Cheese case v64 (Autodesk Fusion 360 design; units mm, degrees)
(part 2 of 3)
sketch "Left outside" plane through (108.8712, 0, 0) normal (1, 0, 0) x axis (0, 0, -1)
  line L1 (127.4117, -56.3921) -> (0, -56.3921)
  line L2 (127.4117, 6.234) -> (127.4117, -56.3921)
  line L3 (0, 6.234) -> (127.4117, 6.234)
  line L4 (0, -56.3921) -> (0, 6.234)
  line L5 (50, 0.8053) -> (0, 0.7957)
  line L6 (4.3132, -90.1692) -> (4.3201, 6.234)
  line L7 (20.5169, -10.8331) -> (9.7193, -10.8352)
  line L8 (9.7193, -10.8352) -> (9.7181, -4.6012)
  line L9 (9.7191, -10) -> (9.7181, -4.6012)
  line L10 (9.7171, 0.7976) -> (9.7181, -4.6012)
  line L11 (20.5159, -5.4343) -> (20.5169, -10.8331)
  line L12 (20.5179, -16.2319) -> (20.5169, -10.8331)
  line L13 (31.3145, -10.8352) -> (31.3133, -4.6012)
  line L14 (31.3123, 0.7976) -> (31.3133, -4.6012)
  line L15 (52.9097, -10.8352) -> (52.9085, -4.6012)
  line L16 (52.9075, 0.7976) -> (52.9085, -4.6012)
  line L17 (74.5049, -10.8352) -> (74.5037, -4.6012)
  line L18 (74.5027, 0.7976) -> (74.5037, -4.6012)
  line L19 (96.1001, -10.8352) -> (96.0989, -4.6012)
  line L20 (96.0979, 0.7976) -> (96.0989, -4.6012)
  line L21 (117.6953, -10.8352) -> (117.6941, -4.6012)
  line L22 (117.6931, 0.7976) -> (117.6941, -4.6012)
  line L23 (9.7193, -23.3032) -> (9.7181, -17.0692)
  line L24 (9.7171, -11.6704) -> (9.7181, -17.0692)
  line L25 (31.3145, -23.3032) -> (31.3133, -17.0692)
  line L26 (31.3123, -11.6704) -> (31.3133, -17.0692)
  line L27 (52.9097, -23.3032) -> (52.9085, -17.0692)
  line L28 (52.9075, -11.6704) -> (52.9085, -17.0692)
  line L29 (74.5049, -23.3032) -> (74.5037, -17.0692)
  line L30 (74.5027, -11.6704) -> (74.5037, -17.0692)
  line L31 (96.1001, -23.3032) -> (96.0989, -17.0692)
  line L32 (96.0979, -11.6704) -> (96.0989, -17.0692)
  line L33 (117.6953, -23.3032) -> (117.6941, -17.0692)
  line L34 (117.6931, -11.6704) -> (117.6941, -17.0692)
  line L35 (9.7193, -35.7712) -> (9.7181, -29.5372)
  line L36 (9.7171, -24.1384) -> (9.7181, -29.5372)
  line L37 (31.3145, -35.7712) -> (31.3133, -29.5372)
  line L38 (31.3123, -24.1384) -> (31.3133, -29.5372)
  line L39 (52.9097, -35.7712) -> (52.9085, -29.5372)
  line L40 (52.9075, -24.1384) -> (52.9085, -29.5372)
  line L41 (74.5049, -35.7712) -> (74.5037, -29.5372)
  line L42 (74.5027, -24.1384) -> (74.5037, -29.5372)
  line L43 (96.1001, -35.7712) -> (96.0989, -29.5372)
  line L44 (96.0979, -24.1384) -> (96.0989, -29.5372)
  line L45 (117.6953, -35.7712) -> (117.6941, -29.5372)
  line L46 (117.6931, -24.1384) -> (117.6941, -29.5372)
  line L47 (9.7193, -48.2392) -> (9.7181, -42.0052)
  line L48 (9.7171, -36.6064) -> (9.7181, -42.0052)
  line L49 (31.3145, -48.2392) -> (31.3133, -42.0052)
  line L50 (31.3123, -36.6064) -> (31.3133, -42.0052)
  line L51 (52.9097, -48.2392) -> (52.9085, -42.0052)
  line L52 (52.9075, -36.6064) -> (52.9085, -42.0052)
  line L53 (74.5049, -48.2392) -> (74.5037, -42.0052)
  line L54 (74.5027, -36.6064) -> (74.5037, -42.0052)
  line L55 (96.1001, -48.2392) -> (96.0989, -42.0052)
  line L56 (96.0979, -36.6064) -> (96.0989, -42.0052)
  line L57 (117.6953, -48.2392) -> (117.6941, -42.0052)
  line L58 (117.6931, -36.6064) -> (117.6941, -42.0052)
  line L59 (42.1131, -16.2319) -> (42.1121, -10.8331)
  line L60 (42.1111, -5.4343) -> (42.1121, -10.8331)
  line L61 (63.7084, -16.2319) -> (63.7073, -10.8331)
  line L62 (63.7063, -5.4343) -> (63.7073, -10.8331)
  line L63 (85.3036, -16.2319) -> (85.3025, -10.8331)
  line L64 (85.3015, -5.4343) -> (85.3025, -10.8331)
  line L65 (106.8988, -16.2319) -> (106.8977, -10.8331)
  line L66 (106.8967, -5.4343) -> (106.8977, -10.8331)
  line L67 (20.5179, -28.6999) -> (20.5169, -23.3011)
  line L68 (20.5159, -17.9023) -> (20.5169, -23.3011)
  line L69 (42.1131, -28.6999) -> (42.1121, -23.3011)
  line L70 (42.1111, -17.9023) -> (42.1121, -23.3011)
  line L71 (63.7084, -28.6999) -> (63.7073, -23.3011)
  line L72 (63.7063, -17.9023) -> (63.7073, -23.3011)
  line L73 (85.3036, -28.6999) -> (85.3025, -23.3011)
  line L74 (85.3015, -17.9023) -> (85.3025, -23.3011)
  line L75 (106.8988, -28.6999) -> (106.8977, -23.3011)
  line L76 (106.8967, -17.9023) -> (106.8977, -23.3011)
  line L77 (20.5179, -41.1679) -> (20.5169, -35.7691)
  line L78 (20.5159, -30.3703) -> (20.5169, -35.7691)
  line L79 (42.1131, -41.1679) -> (42.1121, -35.7691)
  line L80 (42.1111, -30.3703) -> (42.1121, -35.7691)
  line L81 (63.7084, -41.1679) -> (63.7073, -35.7691)
  line L82 (63.7063, -30.3703) -> (63.7073, -35.7691)
  line L83 (85.3036, -41.1679) -> (85.3025, -35.7691)
  line L84 (85.3015, -30.3703) -> (85.3025, -35.7691)
  line L85 (106.8988, -41.1679) -> (106.8977, -35.7691)
  line L86 (106.8967, -30.3703) -> (106.8977, -35.7691)
  line L87 (20.5179, -53.6359) -> (20.5169, -48.2371)
  line L88 (20.5159, -42.8383) -> (20.5169, -48.2371)
  line L89 (42.1131, -53.6359) -> (42.1121, -48.2371)
  line L90 (42.1111, -42.8383) -> (42.1121, -48.2371)
  line L91 (63.7084, -53.6359) -> (63.7073, -48.2371)
  line L92 (63.7063, -42.8383) -> (63.7073, -48.2371)
  line L93 (85.3036, -53.6359) -> (85.3025, -48.2371)
  line L94 (85.3015, -42.8383) -> (85.3025, -48.2371)
  line L95 (106.8988, -53.6359) -> (106.8977, -48.2371)
  line L96 (106.8967, -42.8383) -> (106.8977, -48.2371)
  line L97 (31.3143, -10) -> (31.3133, -4.6012)
  line L98 (52.9095, -10) -> (52.9085, -4.6012)
  line L99 (74.5048, -10) -> (74.5037, -4.6012)
  line L100 (96.1, -10) -> (96.0989, -4.6012)
  line L101 (117.6952, -10) -> (117.6941, -4.6012)
  line L102 (9.7191, -22.468) -> (9.7181, -17.0692)
  line L103 (31.3143, -22.468) -> (31.3133, -17.0692)
  line L104 (52.9095, -22.468) -> (52.9085, -17.0692)
  line L105 (74.5048, -22.468) -> (74.5037, -17.0692)
  line L106 (96.1, -22.468) -> (96.0989, -17.0692)
  line L107 (117.6952, -22.468) -> (117.6941, -17.0692)
  line L108 (9.7191, -34.936) -> (9.7181, -29.5372)
  line L109 (31.3143, -34.936) -> (31.3133, -29.5372)
  line L110 (52.9095, -34.936) -> (52.9085, -29.5372)
  line L111 (74.5048, -34.936) -> (74.5037, -29.5372)
  line L112 (96.1, -34.936) -> (96.0989, -29.5372)
  line L113 (117.6952, -34.936) -> (117.6941, -29.5372)
  line L114 (9.7191, -47.404) -> (9.7181, -42.0052)
  line L115 (31.3143, -47.404) -> (31.3133, -42.0052)
  line L116 (52.9095, -47.404) -> (52.9085, -42.0052)
  line L117 (74.5048, -47.404) -> (74.5037, -42.0052)
  line L118 (96.1, -47.404) -> (96.0989, -42.0052)
  line L119 (117.6952, -47.404) -> (117.6941, -42.0052)
  circle C1 centre (9.7181, -4.6012) radius 5.3988
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  point P11 (9.7181, -4.6012)
  point P12 (9.7181, -4.6012)
  point P14 (20.5169, -10.8331)
  point P15 (20.5169, -10.8331)
  point P16 (9.7191, -10)
  point P17 (9.7171, 0.7976)
  point P18 (20.5169, -10.8331)
  point P20 (20.5169, -10.8331)
  point P13 (9.7193, -10.8352)
  tangent L5 C1
  tangent L6 C1
  coincident P11 P12
  perpendicular L7 L8
  coincident P14 P15
  coincident L8 P16
  coincident C1 P16
  perpendicular L5 L9
  coincident L5 P17
  coincident C1 P17
  perpendicular L5 L10
  coincident P15 P18
  perpendicular L7 L11
  coincident P15 P20
  perpendicular L7 L12
  dimension "d404" radius C1 = 5.3988 (= "radius")
  dimension "d405" distance P12 P13 = 6.234 (= "Linear Dimension-2")
  dimension "d406" distance P13 P14 = 10.7976 (= "2 * radius")
  dimension "d407" diameter = 10.7976 (= "2 * radius")
  dimension "d410" R-Pattern1-uDistance = 21.5952 (= "4 * radius")
  dimension "d414" R-Pattern2-uDistance = 21.5952 (= "4 * radius")
sketch "Left inside" plane through (102.6372, 0, 0) normal (-1, 0, 0) x axis (0, 0, 1)
  line L1 (-127.4117, 6.234) -> (0, 6.234)
  line L2 (-127.4117, -56.3921) -> (-127.4117, 6.234)
  line L3 (0, -56.3921) -> (-127.4117, -56.3921)
  line L4 (0, 6.234) -> (0, -56.3921)
  line L5 (-7.9182, -10.7976) -> (-13.317, -10.7976)
  line L6 (-18.7158, -10.7976) -> (-13.317, -10.7976)
  line L7 (-29.5135, -17.0316) -> (-24.1147, -17.0316)
  line L8 (-18.7158, -17.0316) -> (-24.1147, -17.0316)
  line L9 (-18.7158, -23.2656) -> (-13.317, -23.2656)
  line L10 (-7.9182, -23.2656) -> (-13.317, -23.2656)
  line L11 (-18.7158, -35.7336) -> (-13.317, -35.7336)
  line L12 (-7.9182, -35.7336) -> (-13.317, -35.7336)
  line L13 (-18.7158, -48.2016) -> (-13.317, -48.2016)
  line L14 (-7.9182, -48.2016) -> (-13.317, -48.2016)
  line L15 (-40.3111, -10.7976) -> (-34.9123, -10.7976)
  line L16 (-29.5135, -10.7976) -> (-34.9123, -10.7976)
  line L17 (-40.3111, -23.2656) -> (-34.9123, -23.2656)
  line L18 (-29.5135, -23.2656) -> (-34.9123, -23.2656)
  line L19 (-40.3111, -35.7336) -> (-34.9123, -35.7336)
  line L20 (-29.5135, -35.7336) -> (-34.9123, -35.7336)
  line L21 (-40.3111, -48.2016) -> (-34.9123, -48.2016)
  line L22 (-29.5135, -48.2016) -> (-34.9123, -48.2016)
  line L23 (-61.9063, -10.7976) -> (-56.5075, -10.7976)
  line L24 (-51.1087, -10.7976) -> (-56.5075, -10.7976)
  line L25 (-61.9063, -23.2656) -> (-56.5075, -23.2656)
  line L26 (-51.1087, -23.2656) -> (-56.5075, -23.2656)
  line L27 (-61.9063, -35.7336) -> (-56.5075, -35.7336)
  line L28 (-51.1087, -35.7336) -> (-56.5075, -35.7336)
  line L29 (-61.9063, -48.2016) -> (-56.5075, -48.2016)
  line L30 (-51.1087, -48.2016) -> (-56.5075, -48.2016)
  line L31 (-83.5015, -10.7976) -> (-78.1027, -10.7976)
  line L32 (-72.7039, -10.7976) -> (-78.1027, -10.7976)
  line L33 (-83.5015, -23.2656) -> (-78.1027, -23.2656)
  line L34 (-72.7039, -23.2656) -> (-78.1027, -23.2656)
  line L35 (-83.5015, -35.7336) -> (-78.1027, -35.7336)
  line L36 (-72.7039, -35.7336) -> (-78.1027, -35.7336)
  line L37 (-83.5015, -48.2016) -> (-78.1027, -48.2016)
  line L38 (-72.7039, -48.2016) -> (-78.1027, -48.2016)
  line L39 (-105.0967, -10.7976) -> (-99.6979, -10.7976)
  line L40 (-94.2991, -10.7976) -> (-99.6979, -10.7976)
  line L41 (-105.0967, -23.2656) -> (-99.6979, -23.2656)
  line L42 (-94.2991, -23.2656) -> (-99.6979, -23.2656)
  line L43 (-105.0967, -35.7336) -> (-99.6979, -35.7336)
  line L44 (-94.2991, -35.7336) -> (-99.6979, -35.7336)
  line L45 (-105.0967, -48.2016) -> (-99.6979, -48.2016)
  line L46 (-94.2991, -48.2016) -> (-99.6979, -48.2016)
  line L47 (-126.6919, -10.7976) -> (-121.2931, -10.7976)
  line L48 (-115.8943, -10.7976) -> (-121.2931, -10.7976)
  line L49 (-126.6919, -23.2656) -> (-121.2931, -23.2656)
  line L50 (-115.8943, -23.2656) -> (-121.2931, -23.2656)
  line L51 (-126.6919, -35.7336) -> (-121.2931, -35.7336)
  line L52 (-115.8943, -35.7336) -> (-121.2931, -35.7336)
  line L53 (-126.6919, -48.2016) -> (-121.2931, -48.2016)
  line L54 (-115.8943, -48.2016) -> (-121.2931, -48.2016)
  line L55 (-29.5135, -29.4996) -> (-24.1147, -29.4996)
  line L56 (-18.7158, -29.4996) -> (-24.1147, -29.4996)
  line L57 (-29.5135, -41.9676) -> (-24.1147, -41.9676)
  line L58 (-18.7158, -41.9676) -> (-24.1147, -41.9676)
  line L59 (-51.1087, -17.0316) -> (-45.7099, -17.0316)
  line L60 (-40.3111, -17.0316) -> (-45.7099, -17.0316)
  line L61 (-51.1087, -29.4996) -> (-45.7099, -29.4996)
  line L62 (-40.3111, -29.4996) -> (-45.7099, -29.4996)
  line L63 (-51.1087, -41.9676) -> (-45.7099, -41.9676)
  line L64 (-40.3111, -41.9676) -> (-45.7099, -41.9676)
  line L65 (-72.7039, -17.0316) -> (-67.3051, -17.0316)
  line L66 (-61.9063, -17.0316) -> (-67.3051, -17.0316)
  line L67 (-72.7039, -29.4996) -> (-67.3051, -29.4996)
  line L68 (-61.9063, -29.4996) -> (-67.3051, -29.4996)
  line L69 (-72.7039, -41.9676) -> (-67.3051, -41.9676)
  line L70 (-61.9063, -41.9676) -> (-67.3051, -41.9676)
  line L71 (-94.2991, -17.0316) -> (-88.9003, -17.0316)
  line L72 (-83.5015, -17.0316) -> (-88.9003, -17.0316)
  line L73 (-94.2991, -29.4996) -> (-88.9003, -29.4996)
  line L74 (-83.5015, -29.4996) -> (-88.9003, -29.4996)
  line L75 (-94.2991, -41.9676) -> (-88.9003, -41.9676)
  line L76 (-83.5015, -41.9676) -> (-88.9003, -41.9676)
  line L77 (-115.8943, -17.0316) -> (-110.4955, -17.0316)
  line L78 (-105.0967, -17.0316) -> (-110.4955, -17.0316)
  line L79 (-115.8943, -29.4996) -> (-110.4955, -29.4996)
  line L80 (-105.0967, -29.4996) -> (-110.4955, -29.4996)
  line L81 (-115.8943, -41.9676) -> (-110.4955, -41.9676)
  line L82 (-105.0967, -41.9676) -> (-110.4955, -41.9676)
  line L83 (-51.1087, -17.0316) -> (-45.7099, -17.0316)
  line L84 (-40.3111, -17.0316) -> (-45.7099, -17.0316)
  line L85 (-72.7039, -17.0316) -> (-67.3051, -17.0316)
  line L86 (-61.9063, -17.0316) -> (-67.3051, -17.0316)
  line L87 (-94.2991, -17.0316) -> (-88.9003, -17.0316)
  line L88 (-83.5015, -17.0316) -> (-88.9003, -17.0316)
  line L89 (-115.8943, -17.0316) -> (-110.4955, -17.0316)
  line L90 (-105.0967, -17.0316) -> (-110.4955, -17.0316)
  line L91 (-29.5135, -4.5636) -> (-24.1147, -4.5636)
  line L92 (-18.7158, -4.5636) -> (-24.1147, -4.5636)
  line L93 (-51.1087, -4.5636) -> (-45.7099, -4.5636)
  line L94 (-40.3111, -4.5636) -> (-45.7099, -4.5636)
  line L95 (-72.7039, -4.5636) -> (-67.3051, -4.5636)
  line L96 (-61.9063, -4.5636) -> (-67.3051, -4.5636)
  line L97 (-94.2991, -4.5636) -> (-88.9003, -4.5636)
  line L98 (-83.5015, -4.5636) -> (-88.9003, -4.5636)
  line L99 (-115.8943, -4.5636) -> (-110.4955, -4.5636)
  line L100 (-105.0967, -4.5636) -> (-110.4955, -4.5636)
  circle C1 centre (-13.317, -10.7976) radius 5.3988
  circle C2 centre (-24.1147, -17.0316) radius 5.3988
  circle C3 centre (-13.317, -23.2656) radius 5.3988
  circle C4 centre (-13.317, -35.7336) radius 5.3988
  circle C5 centre (-13.317, -48.2016) radius 5.3988
  circle C6 centre (-34.9123, -10.7976) radius 5.3988
  circle C7 centre (-34.9123, -23.2656) radius 5.3988
  circle C8 centre (-34.9123, -35.7336) radius 5.3988
  circle C9 centre (-34.9123, -48.2016) radius 5.3988
  circle C10 centre (-56.5075, -10.7976) radius 5.3988
  circle C11 centre (-56.5075, -23.2656) radius 5.3988
  circle C12 centre (-56.5075, -35.7336) radius 5.3988
  circle C13 centre (-56.5075, -48.2016) radius 5.3988
  circle C14 centre (-78.1027, -10.7976) radius 5.3988
  circle C15 centre (-78.1027, -23.2656) radius 5.3988
  circle C16 centre (-78.1027, -35.7336) radius 5.3988
  circle C17 centre (-78.1027, -48.2016) radius 5.3988
  circle C18 centre (-99.6979, -10.7976) radius 5.3988
  circle C19 centre (-99.6979, -23.2656) radius 5.3988
  circle C20 centre (-99.6979, -35.7336) radius 5.3988
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  point P9 (-13.317, -10.7976)
  point P13 (-13.317, -10.7976)
  point P11 (-24.1147, -17.0316)
  point P15 (-24.1147, -17.0316)
  point P17 (-24.1147, -17.0316)
  point P14 (-18.7158, -10.7976)
  point P10 (-7.9182, -10.7976)
  point P16 (-18.7158, -17.0316)
  point P18 (-29.5135, -17.0316)
  coincident P9 P13
  coincident P11 P15
  coincident P15 P17
  dimension "d439" diameter C1 = 10.7976 (= "2 * radius")
  dimension "d440" distance P13 P14 = 5.3988 (= "radius")
  dimension "d441" distance P10 P13 = 5.3988 (= "radius")
  dimension "d442" diameter C2 = 10.7976 (= "2 * radius")
  dimension "d443" distance P11 P16 = 5.3988 (= "radius")
  dimension "d444" distance P17 P18 = 5.3988 (= "radius")
  dimension "d448" R-Pattern1-vDistance = 21.5952 (= "4 * radius")
  dimension "d452" R-Pattern2-vDistance = 21.5952 (= "4 * radius")
  dimension "d455" R-Pattern3-uDistance = -21.5952 (= "-4 * radius")
revolve "Revolve61" sketch "Left outside" AlongAngle 360
revolve "Revolve62" sketch "Left outside" AlongAngle 360
revolve "Revolve63" sketch "Left outside" AlongAngle 360
revolve "Revolve64" sketch "Left outside" AlongAngle 360
revolve "Revolve65" sketch "Left outside" AlongAngle 360
revolve "Revolve66" sketch "Left outside" AlongAngle 360
revolve "Revolve67" sketch "Left outside" AlongAngle 360
revolve "Revolve68" sketch "Left outside" AlongAngle 360
revolve "Revolve69" sketch "Left outside" AlongAngle 360
revolve "Revolve70" sketch "Left outside" AlongAngle 360
revolve "Revolve71" sketch "Left outside" AlongAngle 360
revolve "Revolve72" sketch "Left inside" AlongAngle 360
revolve "Revolve73" sketch "Left inside" AlongAngle 360
revolve "Revolve74" sketch "Left inside" AlongAngle 360
revolve "Revolve75" sketch "Left inside" AlongAngle 360
revolve "Revolve76" sketch "Left inside" AlongAngle 360
revolve "Revolve77" sketch "Left inside" AlongAngle 360
revolve "Revolve78" sketch "Left inside" AlongAngle 360
work_plane "WorkPlane2"
mirror "Mirror5" bodies "Rechts"
combine "Combine3" bodies "Links", "Deckel", "Rechts", "Vorne"
fillet "Fillet4" radius 5.3988 (= "radius")
combine "Combine4"
combine "Combine5"
combine "Combine6"
combine "Combine7"
combine "Combine8"
extrude "Extrude16" add sketch "Feet" profile of C1 C2 C3 C4 C5 C6 C7 C8 along normal blind 2.5
extrude "Extrude17" add of existing geometry to an object
extrude "Extrude18" cut sketch "Feet" profile of C1 C2 C3 C4 C5 C6 C7 C8 along normal blind 2.5
chamfer "Chamfer5" distance 2.5
extrude "Extrude10" add sketch "Switch" profile of C1 C2 no distance stored
extrude "Extrude11" cut sketch "Switch" profile of C1 L6 L7 L8 L9 L11 L12 L13 L15 no distance stored
extrude "Extrude12" cut sketch "Switch" profile of C1 C3 L6 L7 L8 L9 L11 L12 L13 L15 no distance stored
extrude "Extrude13" add sketch "Switch" profile of C1 C2 C3 L6 L7 L8 L9 L11 L12 L13 L15 blind -2.5 from offset -2
extrude "Extrude15" add sketch "Switch" profile of C1 C3 L6 L7 L8 L9 L11 L12 L13 L15 blind 0.2 from offset -2
chamfer "Chamfer6" distance 0.4
sketch "Back" plane through (0, 0, -127.4117) normal (0, 0, -1) x axis (-1, 0, 0)
  line L1 (-108.8712, -50.1581) -> (0, -50.1581)
  line L2 (-108.8712, -56.3921) -> (-108.8712, -50.1581)
  line L3 (0, -56.3921) -> (-108.8712, -56.3921)
  line L4 (0, -50.1581) -> (0, -56.3921)
  line L5 (-6.234, 0) -> (-102.6372, 0)
  line L6 (-102.6372, -56.3921) -> (-102.6372, 6.234)
  line L7 (0, -50.1581) -> (-108.8712, -50.1581)
  line L8 (-54.4356, 0) -> (-54.4356, -50.1581)
  line L9 (-44.9562, 0) -> (-6.234, 0)
  line L10 (-6.234, -50.1581) -> (-44.9562, -50.1581)
  line L11 (-6.234, 0) -> (-6.234, -50.1581)
  line L12 (-6.5586, -3.5) -> (-8.1463, -6.25)
  line L13 (-8.1463, -0.75) -> (-6.5586, -3.5)
  line L14 (-11.3217, -0.75) -> (-8.1463, -0.75)
  line L15 (-12.9094, -3.5) -> (-11.3217, -0.75)
  line L16 (-11.3217, -6.25) -> (-12.9094, -3.5)
  line L17 (-8.1463, -6.25) -> (-11.3217, -6.25)
  line L18 (-6.234, -56.3921) -> (-6.234, 6.234)
  line L19 (-103.4724, 6.234) -> (-5.3988, 6.234)
  line L20 (-108.8712, -50.9933) -> (-108.8712, 0.8352)
  line L21 (-5.3988, -56.3921) -> (-103.4724, -56.3921)
  line L22 (0, 0.8352) -> (0, -50.9933)
  line L23 (-6.234, -50.1581) -> (-6.234, 0)
  line L24 (-102.6372, -50.1581) -> (-6.234, -50.1581)
  line L25 (-102.6372, 0) -> (-102.6372, -50.1581)
  line L26 (-6.234, 0) -> (-102.6372, 0)
  line L27 (-86.8562, -21.1) -> (-71.1562, -21.1)
  line L28 (-86.8562, -36.9) -> (-86.8562, -21.1)
  line L29 (-71.1562, -36.9) -> (-86.8562, -36.9)
  line L30 (-71.1562, -21.1) -> (-71.1562, -36.9)
  line L31 (-86.8562, -36.9) -> (-71.1562, -21.1)
  line L32 (-71.1562, -36.9) -> (-86.8562, -21.1)
  line L33 (-68.8562, -36.9) -> (-53.1562, -36.9)
  line L34 (-68.8562, -21.1) -> (-68.8562, -36.9)
  line L35 (-53.1562, -21.1) -> (-68.8562, -21.1)
  line L36 (-53.1562, -36.9) -> (-53.1562, -21.1)
  line L37 (-68.8562, -21.1) -> (-53.1562, -36.9)
  line L38 (-53.1562, -21.1) -> (-68.8562, -36.9)
  line L39 (-102.6372, -17.25) -> (-6.234, -17.25)
  line L40 (-102.6372, -18.92) -> (-102.6372, -17.25)
  line L41 (-6.234, -18.92) -> (-102.6372, -18.92)
  line L42 (-6.234, -17.25) -> (-6.234, -18.92)
  line L43 (-102.6372, -25.0791) -> (-6.234, -25.0791)
  line L44 (-54.4356, 0) -> (-54.4356, -25.0791)
  line L45 (-6.234, -12.5395) -> (-54.4356, -12.5395)
  line L46 (-102.6372, 0) -> (-102.6372, -25.0791)
  line L47 (-54.4356, -12.5395) -> (-102.6372, -12.5395)
  line L48 (-71.1562, 0) -> (-71.1562, -21.1)
  line L49 (-103.6786, -10.55) -> (-71.1562, -10.55)
  line L50 (-3.3486, -10.55) -> (-71.1562, -10.55)
  line L51 (-102.6372, 0) -> (-54.4356, 0)
  line L52 (-78.5364, -12.5395) -> (-78.5364, 0)
  line L53 (-6.234, 0) -> (-54.4356, 0)
  line L54 (-30.3348, -25.0791) -> (-30.3348, 0)
  line L55 (-6.234, -17.25) -> (-6.234, -10.55)
  line L56 (-6.234, -21.1) -> (-6.234, -10.55)
  line L57 (-99, -21.1) -> (-6.234, -21.1)
  line L58 (-6.234, -28.2625) -> (-34.0562, -28.2625)
  curve K1 (-33.3724, -8.0089) -> (-27.7523, -8.0089)
  curve K2 (-33.3724, -18.0089) -> (-33.3724, -8.0089)
  curve K3 (-27.7523, -18.0089) -> (-33.3724, -18.0089)
  curve K4 (-27.7523, -8.0089) -> (-27.7523, -18.0089)
  curve K5 (-81.4952, -8.1924) -> (-75.963, -8.1924)
  curve K6 (-81.4952, -18.1924) -> (-81.4952, -8.1924)
  curve K7 (-75.963, -18.1924) -> (-81.4952, -18.1924)
  curve K8 (-75.963, -8.1924) -> (-75.963, -18.1924)
  line L59 (-71.1562, -36.9) -> (-86.8562, -36.9)
  line L60 (-71.1562, -37.3) -> (-71.1562, -36.9)
  line L61 (-86.8562, -37.3) -> (-71.1562, -37.3)
  line L62 (-86.8562, -36.9) -> (-86.8562, -37.3)
  line L63 (-53.1562, -36.9) -> (-68.8562, -36.9)
  line L64 (-53.1562, -37.3) -> (-53.1562, -36.9)
  line L65 (-68.8562, -37.3) -> (-53.1562, -37.3)
  line L66 (-68.8562, -36.9) -> (-68.8562, -37.3)
  line L67 (-50.4561, -35.6125) -> (-34.0549, -35.6125)
  line L68 (-50.5561, -21.0125) -> (-50.4561, -21.0125)
  line L69 (-50.5561, -35.6125) -> (-50.5561, -21.0125)
  line L70 (-50.4561, -35.6125) -> (-50.5561, -35.6125)
  line L71 (-34.0562, -35.6125) -> (-50.5561, -35.6125)
  line L72 (-50.5561, -20.9125) -> (-34.0562, -20.9125)
  line L73 (-50.5561, -35.6125) -> (-50.5561, -20.9125)
  line L74 (-34.0562, -20.9125) -> (-34.0562, -35.6125)
  circle C1 centre (-42.3852, -10.55) radius 3
  circle C2 centre (-18.2844, -10.55) radius 3
  circle C3 centre (-42.3852, -10.55) radius 6
  circle C4 centre (-18.2844, -10.55) radius 6
  circle C5 centre (-9.734, -3.5) radius 3.5
  circle C6 centre (-99.1372, -3.5) radius 3.5
  circle C7 centre (-99.1372, -46.6581) radius 3.5
  circle C8 centre (-9.734, -46.6581) radius 3.5
  circle C9 centre (-9.734, -3.5) radius 1.6
  circle C10 centre (-9.734, -46.6581) radius 1.6
  circle C11 centre (-99.1372, -3.5) radius 1.6
  circle C12 centre (-99.1372, -46.6581) radius 1.6
  circle C13 centre (-66.486, -10.55) radius 3
  circle C14 centre (-66.486, -10.55) radius 6
  circle C15 centre (-90.5868, -10.55) radius 6
  circle C16 centre (-90.5868, -10.55) radius 3
  circle C17 centre (-42.3852, -10.55) radius 4
  circle C18 centre (-18.2844, -10.55) radius 4
  circle C19 centre (-66.486, -10.55) radius 4
  circle C20 centre (-90.5868, -10.55) radius 4
  arc A1 centre (-5.3988, 0.8352) radius 5.3988 clockwise from (-5.3988, 6.234) to (0, 0.8352)
  arc A2 centre (-103.4724, 0.8352) radius 5.3988 clockwise from (-108.8712, 0.8352) to (-103.4724, 6.234)
  arc A3 centre (-103.4724, -50.9933) radius 5.3988 clockwise from (-103.4724, -56.3921) to (-108.8712, -50.9933)
  arc A4 centre (-5.3988, -50.9933) radius 5.3988 clockwise from (0, -50.9933) to (-5.3988, -56.3921)
  circle C21 centre (-18.2844, -10.55) radius 6.5
  circle C22 centre (-42.3852, -10.55) radius 6.5
  circle C23 centre (-66.486, -10.55) radius 6.5
  circle C24 centre (-90.5868, -10.55) radius 6.5
  circle C25 centre (-18.2844, -10.55) radius 16.0161
  circle C26 centre (-42.3852, -10.55) radius 16.0161
  circle C27 centre (-20.1451, -28.2625) radius 4
  circle C28 centre (-18.2844, -39.6081) radius 6.5
  point P13 (-54.4356, -50.1581)
  point P18 (-44.9562, -50.1581)
  point P16 (-6.234, 0)
  point P24 (-9.734, -3.5)
  point P38 (-9.734, -3.5)
  point P70 (-79.0062, -29)
  point P75 (-61.0062, -29)
  point P80 (-6.234, -17.25)
  point P84 (-6.234, -25.0791)
  point P85 (-102.6372, -25.0791)
  point P14 (-54.4356, 0)
  point P86 (-54.4356, -25.0791)
  point P87 (-54.4356, -25.0791)
  point P88 (-54.4356, -12.5395)
  point P89 (-6.234, -12.5395)
  point P90 (-102.6372, -12.5395)
  point P91 (-71.1562, 0)
  point P92 (-71.1562, -10.55)
  point P95 (-78.5364, 0)
  point P96 (-78.5364, -12.5395)
  point P97 (-30.3348, 0)
  point P98 (-30.3348, -25.0791)
  point P99 (-6.234, -10.55)
  point P100 (-6.234, -10.55)
  point P101 (-6.234, -10.55)
  point P102 (-6.234, -21.1)
  point P76 (-18.2844, -10.55)
  point P104 (-18.2844, -10.55)
  point P21 (-18.2844, -10.55)
  point P23 (-18.2844, -10.55)
  point P43 (-42.3852, -10.55)
  point P105 (-42.3852, -10.55)
  point P107 (-6.234, -28.2625)
  point P108 (-20.1451, -28.2625)
  point P106 (-34.0562, -28.2625)
  point P67 (-86.8562, -21.1)
  point P68 (-86.8562, -36.9)
  point P69 (-71.1562, -36.9)
  point P72 (-68.8562, -36.9)
  point P73 (-68.8562, -21.1)
  point P74 (-53.1562, -21.1)
  point P83 (-6.234, -18.92)
  point P62 (-6.234, 0)
  point P79 (-90.5868, -10.55)
  point P120 (-86.8562, -37.3)
  point P123 (-68.8562, -37.3)
  point P127 (-50.5561, -35.6125)
  point P131 (-50.5561, -20.9125)
  midpoint L7 P13
  horizontal L9
  horizontal L10
  vertical L11
  coincident L7 P18
  coincident L5 P16
  concentric C1 C3
  tangent L9 C5
  tangent L11 C5
  tangent L6 C6
  tangent L5 C6
  tangent L6 C7
  tangent L7 C7
  tangent L10 C8
  tangent L11 C8
  concentric C5 C9
  concentric C8 C10
  concentric C6 C11
  concentric C7 C12
  coincident P24 P38
  symmetric L8 C1 C13
  symmetric L8 C2 C16
  symmetric L8 C3 C14
  symmetric L8 C4 C15
  concentric C3 C17
  concentric C2 C18
  concentric C13 C19
  concentric C15 C20
  perpendicular L27 L28
  parallel L27 L29
  parallel L28 L30
  horizontal L27
  coincident L31 P70
  coincident L32 P70
  perpendicular L33 L34
  parallel L33 L35
  parallel L34 L36
  horizontal L33
  coincident L37 P75
  coincident L38 P75
  concentric C2 C21
  concentric C1 C22
  concentric C14 C23
  concentric C20 C24
  horizontal L39
  vertical L40
  horizontal L41
  vertical L42
  coincident L11 P80
  coincident L18 P80
  midpoint L18 P84
  midpoint L6 P85
  midpoint L5 P14
  midpoint L43 P86
  coincident P86 P87
  horizontal L45
  midpoint L44 P88
  coincident L11 P89
  midpoint L46 P90
  coincident L5 P91
  perpendicular L5 L48
  midpoint L48 P92
  perpendicular L25 L49
  perpendicular L11 L50
  midpoint L51 P95
  midpoint L47 P96
  midpoint L53 P97
  coincident L43 P98
  perpendicular L43 L54
  coincident L50 P99
  coincident L18 P99
  coincident P99 P100
  coincident P99 P101
  parallel L18 L56
  perpendicular L25 L57
  coincident P102 C25
  coincident P97 C25
  coincident P97 C26
  coincident P76 P104
  coincident P21 P23
  coincident P43 P105
  perpendicular L23 L58
  coincident L23 P107
  midpoint L58 P108
  perpendicular K1 K2
  parallel K1 K3
  parallel K2 K4
  perpendicular K5 K6
  parallel K5 K7
  parallel K6 K8
  symmetric C21 L43 C28
  horizontal L59
  vertical L60
  horizontal L61
  vertical L62
  horizontal L63
  vertical L64
  horizontal L65
  vertical L66
  horizontal L67
  horizontal L68
  vertical L69
  horizontal L70
  horizontal L71
  horizontal L72
  vertical L73
  perpendicular L57 L74
  midpoint P106 L74
  dimension "d372" diameter C1 = 6
  dimension "d373" diameter C2 = 6
  dimension "d374" diameter C3 = 12
  dimension "d377" diameter C4 = 12
  dimension "d381" radius C5 = 3.5
  dimension "d382" radius C6 = 3.5
  dimension "d383" radius C7 = 3.5
  dimension "d384" radius C8 = 3.5
  dimension "d385" diameter C9 = 3.2
  dimension "d386" diameter C10 = 3.2
  dimension "d387" diameter C11 = 3.2
  dimension "d388" diameter C12 = 3.2
  dimension "d394" distance P38 L17 = 2.75
  dimension "d395" diameter C17 = 8
  dimension "d397" diameter C18 = 8
  dimension "d399" diameter C19 = 8
  dimension "d400" diameter C20 = 8
  dimension "d497" distance P67 P68 = 15.8
  dimension "d498" distance P68 P69 = 15.7
  dimension "d499" distance P72 P73 = 15.8
  dimension "d500" distance P73 P74 = 15.7
  dimension "d537" diameter C21 = 13
  dimension "d538" diameter C22 = 13
  dimension "d539" diameter C23 = 13
  dimension "d540" diameter C24 = 13
  dimension "d549" distance P80 P83 = 1.67
  dimension "d550" distance P62 P99 = 10.55
  dimension "d551" distance P101 P102 = 10.55
  dimension "d552" distance P79 L39 = 6.7
  dimension "d577" diameter C27 = 8
  dimension "d620" distance P68 P120 = 0.4
  dimension "d621" distance P72 P123 = 0.4
  dimension "d624" distance P127 P131 = 14.7
extrude "Extrude25" new body sketch "Back" profile of L1 L5 L6 L7 C1 C2 C5 C6 C7 C8 C9 C10 C11 C12 C13 C16 C17 C18 C19 C20 L18 L23 L24 L25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 blind -2 from offset -4 bodies "Back"
extrude "Extrude36" sketch "Back" profile of L1 L5 L6 L7 C5 C6 C7 C8 C9 C10 C11 C12 L18 L23 L24 L25 L26 blind -3
extrude "Extrude26" sketch "Back" profile of C1 C2 C9 C10 C11 C12 C13 C16 L27 L28 L29 L30 L33 L34 L35 L36 C27 L59 L63 L70 L71 L72 L73 L74 blind -2
extrude "Extrude27" sketch "Back" profile of C1 C2 C13 C16 C17 C18 C19 C20 blind -1.2
extrude "Extrude28" sketch "Back" profile of C1 C2 C13 C16 C17 C18 C19 C20 blind 0.2
chamfer "Chamfer13" distance 1
position "Position8"
extrude "Extrude35" sketch "Back" profile of C1 C2 C13 C16 C17 C18 C19 C20 C21 C22 C23 C24 blind -0.8
extrude "Extrude37" sketch "Back" profile of L6 L18 L23 L25 L39 L40 L41 L42 blind -4
offset_faces "OffsetFaces4" distance -0.1
base_feature "Base Feature1" bodies "Holder"
position "Position9"
delete_face "DeleteFace1"
extrude "Extrude2" add of existing geometry to an object
extrude "Extrude1" add of existing geometry blind 3
sketch "Sketch1" plane through (0, 0, 5) normal (0, 0, 1) x axis (1, 0, 0)
  line L1 (55, 58) -> (55, 55.3166)
  line L2 (51, 62) -> (55, 58)
  line L3 (34, 62) -> (51, 62)
  line L4 (34, 66) -> (34, 62)
  line L5 (19, 66) -> (34, 66)
  line L6 (19, 64) -> (19, 66)
  line L7 (0, 64) -> (19, 64)
  line L8 (-6, 58) -> (0, 64)
  line L9 (-6, 55.3166) -> (-6, 58)
  line L10 (-6, 10.3166) -> (-6, 48.6834)
  line L11 (-6, 0.1421) -> (-6, 3.6834)
  line L12 (0.0711, -5.9289) -> (-6, 0.1421)
  line L13 (0, -6) -> (0.0711, -5.9289)
  line L14 (16, -6) -> (0, -6)
  line L15 (16, -4) -> (16, -6)
  line L16 (2.0616, -4) -> (16, -4)
  line L17 (-3.3541, 3) -> (3.3541, 3)
  line L18 (-4, 55.9384) -> (-4, 2.0616)
  line L19 (3.3541, 55) -> (-3.3541, 55)
  line L20 (4, 60.0616) -> (4, 55.9384)
  line L21 (21, 62) -> (2.0616, 62)
  line L22 (21, 64) -> (21, 62)
  line L23 (32, 64) -> (21, 64)
  line L24 (32, 62.1421) -> (32, 64)
  line L25 (34.1421, 60) -> (32, 62.1421)
  line L26 (44.9689, 60) -> (34.1421, 60)
  line L27 (52.3541, 55) -> (45.6459, 55)
  line L28 (53, 2.0616) -> (53, 55.9384)
  line L29 (46, -3.3541) -> (46, 3.3541)
  line L30 (32, -4) -> (46.9384, -4)
  line L31 (32, -6) -> (32, -4)
  line L32 (49, -6) -> (32, -6)
  line L33 (48.9289, -5.9289) -> (49, -6)
  line L34 (55, 0.1421) -> (48.9289, -5.9289)
  line L35 (55, 3.6834) -> (55, 0.1421)
  line L36 (55, 48.6834) -> (55, 10.3166)
  line L37 (-14.2332, 52) -> (-12.6166, 54.8)
  line L38 (-12.6166, 49.2) -> (-14.2332, 52)
  line L39 (-9.3834, 49.2) -> (-12.6166, 49.2)
  line L40 (-7.7668, 52) -> (-9.3834, 49.2)
  line L41 (-9.3834, 54.8) -> (-7.7668, 52)
  line L42 (-12.6166, 54.8) -> (-9.3834, 54.8)
  line L43 (-14.2332, 7) -> (-12.6166, 9.8)
  line L44 (-12.6166, 4.2) -> (-14.2332, 7)
  line L45 (-9.3834, 4.2) -> (-12.6166, 4.2)
  line L46 (-7.7668, 7) -> (-9.3834, 4.2)
  line L47 (-9.3834, 9.8) -> (-7.7668, 7)
  line L48 (-12.6166, 9.8) -> (-9.3834, 9.8)
  line L49 (56.7668, 52) -> (58.3834, 54.8)
  line L50 (58.3834, 49.2) -> (56.7668, 52)
  line L51 (61.6166, 49.2) -> (58.3834, 49.2)
  line L52 (63.2332, 52) -> (61.6166, 49.2)
  line L53 (61.6166, 54.8) -> (63.2332, 52)
  line L54 (58.3834, 54.8) -> (61.6166, 54.8)
  line L55 (56.7668, 7) -> (58.3834, 9.8)
  line L56 (58.3834, 4.2) -> (56.7668, 7)
  line L57 (61.6166, 4.2) -> (58.3834, 4.2)
  line L58 (63.2332, 7) -> (61.6166, 4.2)
  line L59 (61.6166, 9.8) -> (63.2332, 7)
  line L60 (58.3834, 9.8) -> (61.6166, 9.8)
  circle C1 centre (-11, 52) radius 2
  circle C2 centre (60, 7) radius 2
  circle C3 centre (60, 52) radius 2
  circle C4 centre (-11, 7) radius 2
  arc A1 centre (-11, 52) radius 6 clockwise from (-6, 48.6834) to (-6, 55.3166)
  arc A2 centre (-11, 7) radius 6 clockwise from (-6, 3.6834) to (-6, 10.3166)
  arc A3 centre (0, 0) radius 4.5 clockwise from (3.3541, 3) to (2.0616, -4)
  arc A4 centre (0, 0) radius 4.5 clockwise from (-4, 2.0616) to (-3.3541, 3)
  arc A5 centre (0, 58) radius 4.5 clockwise from (-3.3541, 55) to (-4, 55.9384)
  arc A6 centre (0, 58) radius 4.5 clockwise from (4, 55.9384) to (3.3541, 55)
  arc A7 centre (0, 58) radius 4.5 clockwise from (2.0616, 62) to (4, 60.0616)
  arc A8 centre (49, 58) radius 4.5 clockwise from (45.6459, 55) to (44.9689, 60)
  arc A9 centre (49, 58) radius 4.5 clockwise from (53, 55.9384) to (52.3541, 55)
  arc A10 centre (49, 0) radius 4.5 clockwise from (46, 3.3541) to (53, 2.0616)
  arc A11 centre (49, 0) radius 4.5 clockwise from (46.9384, -4) to (46, -3.3541)
  arc A12 centre (60, 7) radius 6 clockwise from (55, 10.3166) to (55, 3.6834)
  arc A13 centre (60, 52) radius 6 clockwise from (55, 55.3166) to (55, 48.6834)
  circle C5 centre (49, 0) radius 1.6
  circle C6 centre (0, 0) radius 1.6
  circle C7 centre (0, 58) radius 1.6
  circle C8 centre (49, 58) radius 1.6
  circle C9 centre (60, 7) radius 2
  circle C10 centre (60, 52) radius 2
  circle C11 centre (-11, 7) radius 2
  circle C12 centre (-11, 52) radius 2
  point P2 (-11, 52)
  point P65 (-11, 52)
  point P5 (-11, 7)
  point P72 (-11, 7)
  point P4 (60, 52)
  point P79 (60, 52)
  point P3 (60, 7)
  point P86 (60, 7)
  coincident P2 P65
  coincident P5 P72
  coincident P4 P79
  coincident P3 P86
  dimension "d560" distance P65 L42 = 2.8 (= "( 5.6 / 2 ) * 1 mm")
  dimension "d561" distance P72 L48 = 2.8 (= "( 5.6 / 2 ) * 1 mm")
  dimension "d562" distance P79 L54 = 2.8 (= "( 5.6 / 2 ) * 1 mm")
  dimension "d563" distance P86 L60 = 2.8 (= "( 5.6 / 2 ) * 1 mm")
extrude "Extrude3" cut sketch "Sketch1" profile of C1 C2 C3 C4 L37 L38 L39 L40 L41 L42 L43 L44 L45 L46 L47 L48 L49 L50 L51 L52 L53 L54 L55 L56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 along a picked direction blind -4.2
position "Position11"
ground "Ground4"
sketch "Halter" plane through (0, 6.234, 0) normal (0, 1, 0) x axis (-1, 0, 0)
  line L1 (-5.3988, -74.5035) -> (-5.3988, -96.0987)
  line L2 (-5.3988, -52.9083) -> (-5.3988, -74.5035)
  line L3 (-5.3988, -31.3131) -> (-5.3988, -52.9083)
  line L4 (-5.3988, 0) -> (-5.3988, -9.7178)
  line L5 (-103.4724, 0) -> (-5.3988, 0)
  line L6 (-103.4724, -9.7178) -> (-103.4724, 0)
  line L7 (-103.4724, -52.9083) -> (-103.4724, -31.3131)
  line L8 (-103.4724, -74.5035) -> (-103.4724, -52.9083)
  line L9 (-103.4724, -96.0987) -> (-103.4724, -74.5035)
  line L10 (-103.4724, -127.4117) -> (-103.4724, -117.6939)
  line L11 (-5.3988, -127.4117) -> (-103.4724, -127.4117)
  line L12 (-5.3988, -117.6939) -> (-5.3988, -127.4117)
  arc A1 centre (-17.8988, -109.5129) radius 12.5 clockwise from (-17.9448, -97.013) to (-16.0943, -97.1439)
  arc A2 centre (-10.7976, -96.0987) radius 5.3988 clockwise from (-16.0943, -97.1439) to (-5.3988, -96.0987)
  circle C1 centre (-10.7976, -74.5035) radius 5.3988
  circle C2 centre (-10.7976, -52.9083) radius 5.3988
  arc A3 centre (-10.7976, -31.3131) radius 5.3988 clockwise from (-5.3988, -31.3131) to (-16.0943, -30.2679)
  arc A4 centre (-17.8988, -17.8988) radius 12.5 clockwise from (-16.0943, -30.2679) to (-17.9448, -30.3987)
  arc A5 centre (-23.2656, -31.3131) radius 5.3988 clockwise from (-17.9448, -30.3987) to (-26.4874, -26.981)
  arc A6 centre (-17.8988, -17.8988) radius 12.5 clockwise from (-26.4874, -26.981) to (-27.7317, -25.6166)
  arc A7 centre (-29.4996, -20.5154) radius 5.3988 clockwise from (-27.7317, -25.6166) to (-30.0927, -15.1493)
  arc A8 centre (-17.8988, -17.8988) radius 12.5 clockwise from (-30.0927, -15.1493) to (-28.4555, -11.2051)
  arc A9 centre (-23.2656, -9.7178) radius 5.3988 clockwise from (-28.4555, -11.2051) to (-19.8345, -5.5496)
  arc A10 centre (-17.8988, -17.8988) radius 12.5 clockwise from (-19.8345, -5.5496) to (-14.5656, -5.8514)
  arc A11 centre (-10.7976, -9.7178) radius 5.3988 clockwise from (-14.5656, -5.8514) to (-5.3988, -9.7178)
  arc A12 centre (-98.0736, -9.7178) radius 5.3988 clockwise from (-103.4724, -9.7178) to (-94.3056, -5.8514)
  arc A13 centre (-90.9724, -17.8988) radius 12.5 clockwise from (-94.3056, -5.8514) to (-89.0367, -5.5496)
  arc A14 centre (-85.6056, -9.7178) radius 5.3988 clockwise from (-89.0367, -5.5496) to (-80.4157, -11.2051)
  arc A15 centre (-90.9724, -17.8988) radius 12.5 clockwise from (-80.4157, -11.2051) to (-78.7785, -15.1493)
  arc A16 centre (-79.3716, -20.5154) radius 5.3988 clockwise from (-78.7785, -15.1493) to (-81.1395, -25.6166)
  arc A17 centre (-90.9724, -17.8988) radius 12.5 clockwise from (-81.1395, -25.6166) to (-82.3838, -26.981)
  arc A18 centre (-85.6056, -31.3131) radius 5.3988 clockwise from (-82.3838, -26.981) to (-90.9264, -30.3987)
  arc A19 centre (-90.9724, -17.8988) radius 12.5 clockwise from (-90.9264, -30.3987) to (-92.7769, -30.2679)
  arc A20 centre (-98.0736, -31.3131) radius 5.3988 clockwise from (-92.7769, -30.2679) to (-103.4724, -31.3131)
  circle C3 centre (-98.0736, -52.9083) radius 5.3988
  circle C4 centre (-98.0736, -74.5035) radius 5.3988
  arc A21 centre (-98.0736, -96.0987) radius 5.3988 clockwise from (-103.4724, -96.0987) to (-92.7769, -97.1439)
  arc A22 centre (-90.9724, -109.5129) radius 12.5 clockwise from (-92.7769, -97.1439) to (-90.9264, -97.013)
  arc A23 centre (-85.6056, -96.0987) radius 5.3988 clockwise from (-90.9264, -97.013) to (-82.3838, -100.4308)
  arc A24 centre (-90.9724, -109.5129) radius 12.5 clockwise from (-82.3838, -100.4308) to (-81.1395, -101.7952)
  arc A25 centre (-79.3716, -106.8963) radius 5.3988 clockwise from (-81.1395, -101.7952) to (-78.7785, -112.2624)
  arc A26 centre (-90.9724, -109.5129) radius 12.5 clockwise from (-78.7785, -112.2624) to (-80.4157, -116.2066)
  arc A27 centre (-85.6056, -117.6939) radius 5.3988 clockwise from (-80.4157, -116.2066) to (-89.0367, -121.8622)
  arc A28 centre (-90.9724, -109.5129) radius 12.5 clockwise from (-89.0367, -121.8622) to (-94.3056, -121.5603)
  arc A29 centre (-98.0736, -117.6939) radius 5.3988 clockwise from (-94.3056, -121.5603) to (-103.4724, -117.6939)
  arc A30 centre (-10.7976, -117.6939) radius 5.3988 clockwise from (-5.3988, -117.6939) to (-14.5656, -121.5603)
  arc A31 centre (-17.8988, -109.5129) radius 12.5 clockwise from (-14.5656, -121.5603) to (-19.8345, -121.8622)
  arc A32 centre (-23.2656, -117.6939) radius 5.3988 clockwise from (-19.8345, -121.8622) to (-28.4555, -116.2066)
  arc A33 centre (-17.8988, -109.5129) radius 12.5 clockwise from (-28.4555, -116.2066) to (-30.0927, -112.2624)
  arc A34 centre (-29.4996, -106.8963) radius 5.3988 clockwise from (-30.0927, -112.2624) to (-27.7317, -101.7952)
  arc A35 centre (-17.8988, -109.5129) radius 12.5 clockwise from (-27.7317, -101.7952) to (-26.4874, -100.4308)
  arc A36 centre (-23.2656, -96.0987) radius 5.3988 clockwise from (-26.4874, -100.4308) to (-17.9448, -97.013)
  circle C5 centre (-41.9676, -63.7059) radius 5.3988
  circle C6 centre (-41.9676, -42.1107) radius 5.3988
  circle C7 centre (-35.7336, -52.9083) radius 5.3988
  circle C8 centre (-79.3716, -63.7059) radius 5.3988
  circle C9 centre (-79.3716, -85.3011) radius 5.3988
  circle C10 centre (-35.7336, -96.0987) radius 5.3988
  circle C11 centre (-35.7336, -117.6939) radius 5.3988
  circle C12 centre (-41.9676, -20.5154) radius 5.3988
  circle C13 centre (-41.9676, -85.3011) radius 5.3988
  circle C14 centre (-17.0316, -63.7059) radius 5.3988
  circle C15 centre (-29.4996, -63.7059) radius 5.3988
  circle C16 centre (-29.4996, -42.1107) radius 5.3988
  circle C17 centre (-48.2016, -31.3131) radius 5.3988
  circle C18 centre (-17.0316, -42.1107) radius 5.3988
  circle C19 centre (-35.7336, -74.5035) radius 5.3988
  circle C20 centre (-35.7336, -9.7178) radius 5.3988
  circle C21 centre (-35.7336, -31.3131) radius 5.3988
  circle C22 centre (-48.2016, -9.7178) radius 5.3988
  circle C23 centre (-17.0316, -85.3011) radius 5.3988
  circle C24 centre (-29.4996, -85.3011) radius 5.3988
  circle C25 centre (-66.9036, -106.8963) radius 5.3988
  circle C26 centre (-73.1376, -31.3131) radius 5.3988
  circle C27 centre (-73.1376, -96.0987) radius 5.3988
  circle C28 centre (-66.9036, -85.3011) radius 5.3988
  circle C29 centre (-66.9036, -42.1107) radius 5.3988
  circle C30 centre (-66.9036, -63.7059) radius 5.3988
  circle C31 centre (-66.9036, -20.5154) radius 5.3988
  circle C32 centre (-60.6696, -117.6939) radius 5.3988
  circle C33 centre (-60.6696, -31.3131) radius 5.3988
  circle C34 centre (-60.6696, -96.0987) radius 5.3988
  circle C35 centre (-60.6696, -9.7178) radius 5.3988
  circle C36 centre (-60.6696, -52.9083) radius 5.3988
  circle C37 centre (-60.6696, -74.5035) radius 5.3988
  circle C38 centre (-54.4356, -106.8963) radius 5.3988
  circle C39 centre (-54.4356, -63.7059) radius 5.3988
  circle C40 centre (-54.4356, -20.5154) radius 5.3988
  circle C41 centre (-54.4356, -85.3011) radius 5.3988
  circle C42 centre (-48.2016, -52.9083) radius 5.3988
  circle C43 centre (-48.2016, -74.5035) radius 5.3988
  circle C44 centre (-48.2016, -117.6939) radius 5.3988
  circle C45 centre (-54.4356, -42.1107) radius 5.3988
  circle C46 centre (-23.2656, -52.9083) radius 5.3988
  circle C47 centre (-23.2656, -74.5035) radius 5.3988
  circle C48 centre (-48.2016, -96.0987) radius 5.3988
  circle C49 centre (-73.1376, -74.5035) radius 5.3988
  circle C50 centre (-73.1376, -117.6939) radius 5.3988
  circle C51 centre (-79.3716, -42.1107) radius 5.3988
  circle C52 centre (-41.9676, -106.8963) radius 5.3988
  circle C53 centre (-73.1376, -9.7178) radius 5.3988
  circle C54 centre (-73.1376, -52.9083) radius 5.3988
  circle C55 centre (-85.6056, -52.9083) radius 5.3988
  circle C56 centre (-85.6056, -74.5035) radius 5.3988
  circle C57 centre (-91.8396, -42.1107) radius 5.3988
  circle C58 centre (-91.8396, -63.7059) radius 5.3988
  circle C59 centre (-91.8396, -85.3011) radius 5.3988
  circle C60 centre (-24.5062, -91.7938) radius 4
  circle C61 centre (-24.5062, -46.7938) radius 4
  circle C62 centre (-95.5062, -46.7938) radius 4
  circle C63 centre (-95.5062, -91.7938) radius 4
  circle C64 centre (-24.5062, -91.7938) radius 2
  circle C65 centre (-24.5062, -46.7938) radius 2
  circle C66 centre (-95.5062, -46.7938) radius 2
  circle C67 centre (-95.5062, -91.7938) radius 2
  circle C68 centre (-24.5062, -46.7938) radius 6
  circle C69 centre (-24.5062, -91.7938) radius 6
  circle C70 centre (-95.5062, -91.7938) radius 6
  circle C71 centre (-95.5062, -46.7938) radius 6
  dimension "d567" = 2
  dimension "d568" = 2
  dimension "d569" = 2
  dimension "d570" = 2
ground "Ground3"
position "Position10"
ground "Ground1"
ground "Ground2"
extrude "Extrude38" add sketch "Halter" profile of C3 A21 A23 A36 C16 C18 C23 C24 C46 C57 C59 C60 C61 C62 C63 C64 C65 C66 C67 C68 C69 C70 C71 no distance stored
extrude "Extrude39" cut sketch "Halter" profile of C3 A21 A36 C16 C46 C57 C64 C65 C66 C67 no distance stored
extrude "Extrude40" cut sketch "Halter" profile of C3 A21 A36 C16 C18 C24 C46 C57 C59 C60 C61 C62 C63 C64 C65 C66 C67 against normal blind 4
extrude "Extrude41" sketch "Back" blind -0.8
sketch "Back Holder" plane through (0, 0, -118.4117) normal (0, 0, 1) x axis (1, 0, 0)
  line L1 (6.4431, -46.6581) -> (8.0886, -43.8081)
  line L2 (8.0886, -49.5081) -> (6.4431, -46.6581)
  line L3 (11.3794, -49.5081) -> (8.0886, -49.5081)
  line L4 (13.0249, -46.6581) -> (11.3794, -49.5081)
  line L5 (11.3794, -43.8081) -> (13.0249, -46.6581)
  line L6 (8.0886, -43.8081) -> (11.3794, -43.8081)
  line L7 (14.234, -50.0581) -> (6.334, -50.0581)
  line L8 (14.234, -42.1581) -> (14.234, -50.0581)
  line L9 (6.334, -42.1581) -> (14.234, -42.1581)
  line L10 (6.334, -50.0581) -> (6.334, -42.1581)
  line L11 (14.234, -43.8081) -> (11.3794, -43.8081)
  line L12 (14.234, -49.5081) -> (11.3794, -49.5081)
  line L13 (6.234, 0) -> (6.234, -50.1581)
  line L14 (6.234, -50.1581) -> (44.9562, -50.1581)
  line L15 (6.234, -50.0581) -> (14.234, -50.0581)
  line L16 (6.234, -50.1581) -> (6.234, -50.0581)
  line L17 (14.234, -50.1581) -> (6.234, -50.1581)
  line L18 (14.234, -50.0581) -> (14.234, -50.1581)
  line L19 (6.234, -42.1581) -> (6.334, -42.1581)
  line L20 (6.234, -50.1581) -> (6.234, -42.1581)
  line L21 (6.334, -50.1581) -> (6.234, -50.1581)
  line L22 (6.334, -42.1581) -> (6.334, -50.1581)
  line L23 (9.734, -50.0581) -> (6.334, -50.0581)
  line L24 (6.334, -50.0581) -> (6.334, -46.6581)
  circle C1 centre (9.734, -46.6581) radius 1.6
  arc A1 centre (9.734, -46.6581) radius 3.4 clockwise from (6.334, -46.6581) to (9.734, -50.0581)
  point P2 (9.734, -46.6581)
  point P11 (9.734, -46.6581)
  point P16 (14.234, -43.8081)
  point P17 (14.234, -49.5081)
  point P18 (6.234, -50.1581)
  point P23 (6.234, -50.1581)
  point P12 (6.334, -50.0581)
  point P13 (14.234, -50.0581)
  point P15 (6.334, -42.1581)
  coincident P2 P11
  horizontal L7
  vertical L8
  horizontal L9
  vertical L10
  coincident L8 P16
  perpendicular L8 L11
  coincident L8 P17
  perpendicular L8 L12
  horizontal L15
  vertical L16
  horizontal L17
  vertical L18
  coincident P18 P23
  horizontal L19
  vertical L20
  horizontal L21
  vertical L22
  dimension "d581" distance P11 L6 = 2.85 (= "( 5.7 / 2 ) * 1 mm")
  dimension "d582" distance P12 P13 = 7.9
  dimension "d583" distance P12 P15 = 7.9
extrude "Extrude42" new body sketch "Back Holder" profile of C1 A1 L1 L2 L3 L4 L5 L6 L7 L8 L9 L10 L11 L12 L13 L14 L15 L16 L17 L18 L19 L20 L21 L22 along normal blind 1
extrude "Extrude43" sketch "Back Holder" profile of A1 L1 L2 L3 L6 L7 L8 L9 L10 L11 L12 L13 L14 L15 L16 L17 L18 L19 L20 L21 L22 blind 2.6
extrude "Extrude44" sketch "Back Holder" profile of C1 A1 L1 L2 L3 L4 L5 L6 L7 L8 L9 L10 L11 L12 L13 L14 L15 L16 L17 L18 L19 L20 L21 L22 blind 1
extrude "Extrude45" sketch "Back" profile of C28 to an object
extrude "Extrude46" sketch "Back Holder" profile of C1 blind -1
mirror "Mirror12"
mirror "Mirror13"
combine "Combine9"
chamfer "Chamfer12" distance 8
extrude "Extrude47" cut sketch "Back" profile of C9 C10 C11 C12 against normal blind 20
